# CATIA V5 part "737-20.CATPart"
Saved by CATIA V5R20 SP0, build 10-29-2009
Part number: 737-20
Definition: NONE
Nomenclature: 737-20
Source: Unknown
Description: 737-20
Bounding box of the stored display mesh (mm): x -25 to 18, y -24.896 to 24.896, z -37 to 15
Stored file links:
  C:\Users\Utente\Desktop\IO LAVORO\3D X SITO CF\X SITO\737\737-20.CATPart
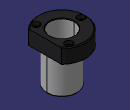
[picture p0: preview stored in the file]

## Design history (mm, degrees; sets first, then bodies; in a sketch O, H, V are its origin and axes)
Body1 "737-20" (main body)
  Solid1: solid without history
